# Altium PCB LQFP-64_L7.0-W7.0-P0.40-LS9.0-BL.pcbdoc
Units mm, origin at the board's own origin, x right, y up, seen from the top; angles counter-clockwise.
Board outline 22.4 x 22.6 mm, 2 copper layers (Top Layer, Bottom Layer); 1 components, 0 nets, 64 pads, 0 vias.
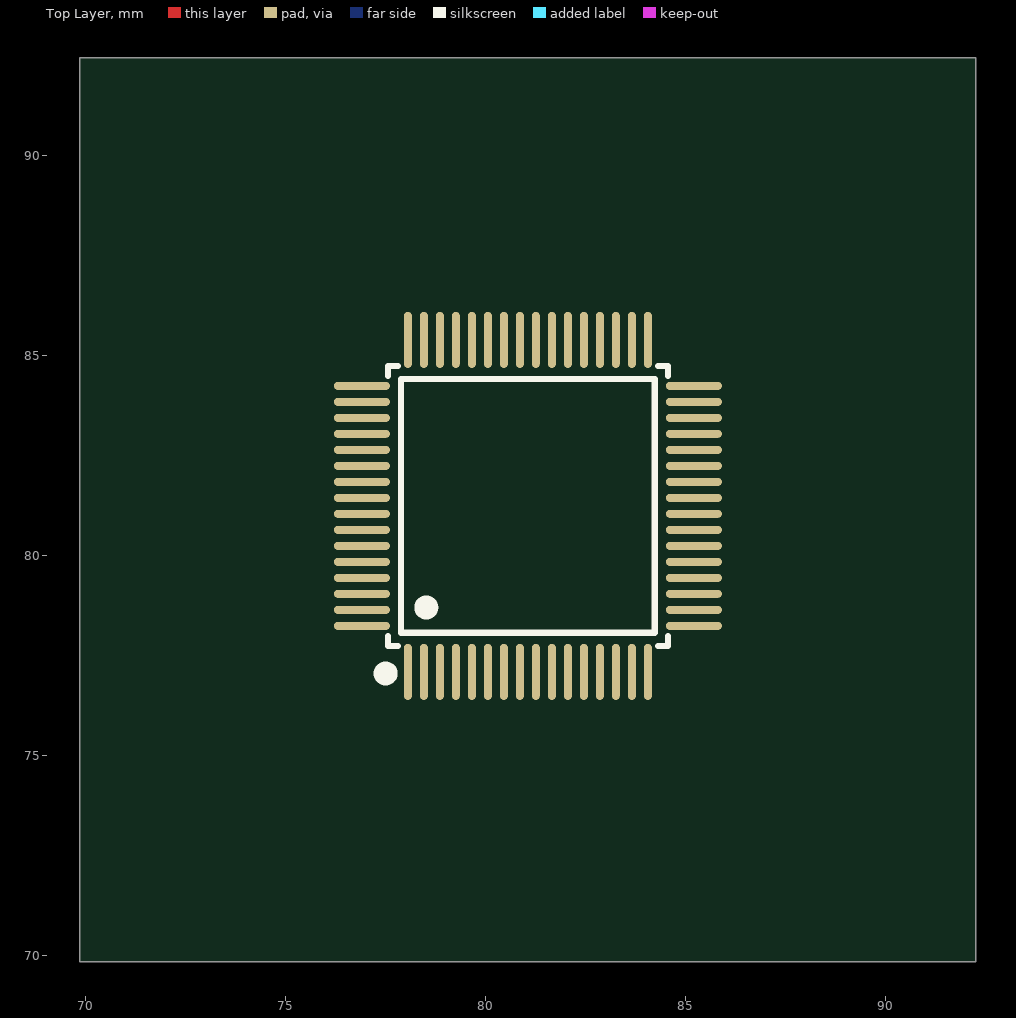
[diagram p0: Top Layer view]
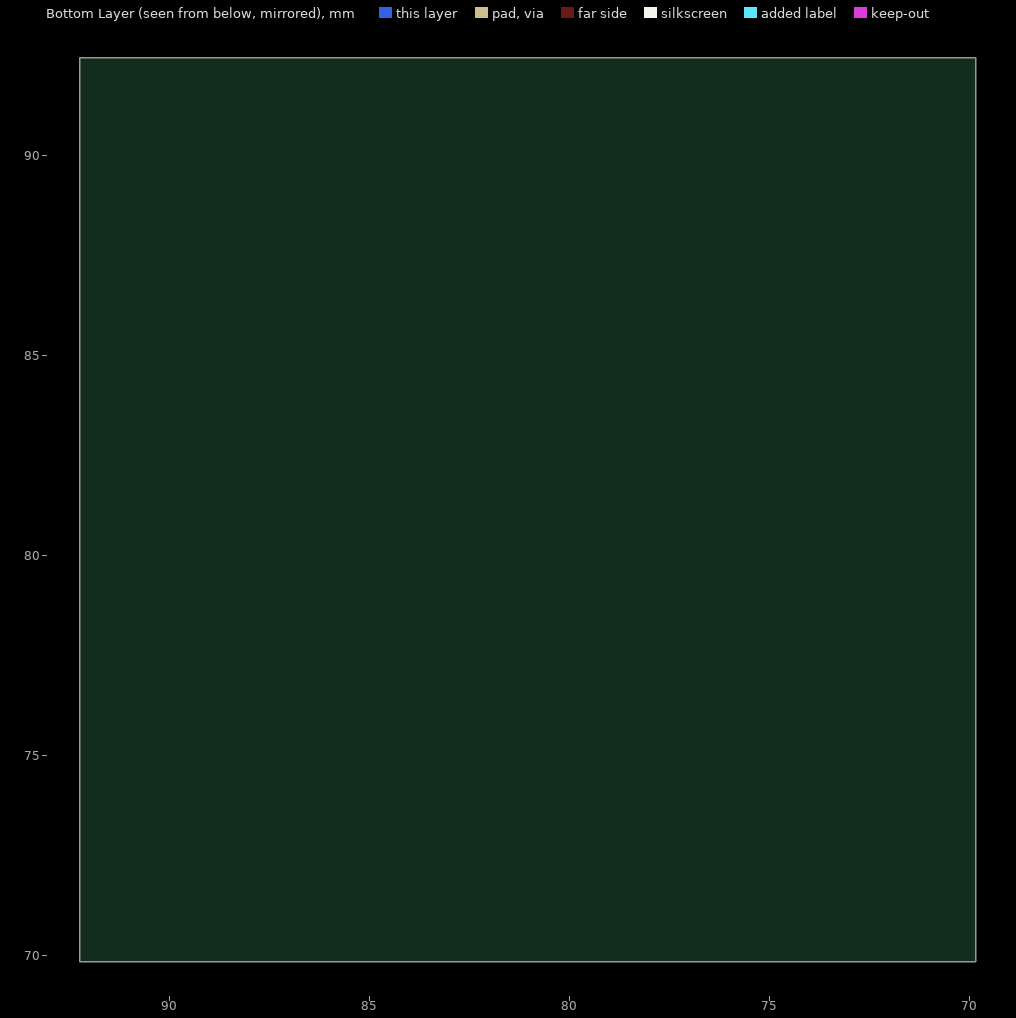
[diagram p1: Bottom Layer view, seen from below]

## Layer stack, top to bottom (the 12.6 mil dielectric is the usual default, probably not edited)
Top Layer: signal copper (thickness not stored)
Dielectric: dielectric 0.32, FR-4, Dk 4.8
Bottom Layer: signal copper (thickness not stored)

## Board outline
92.25,69.85 69.85,69.85 69.85,92.45 92.25,92.45

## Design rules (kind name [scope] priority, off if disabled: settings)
BoardOutlineClearance safeClearance [All] p0: genericclearance=0.254 ignorepadtopadclearanceinfootprint=FALSE except(0: Arc-SplitContinuation Track-SplitContinuation SMDPad-SplitContinuation THPad-SplitContinuation Via-SplitContinuation Fill-SplitContinuation Poly-SplitContinuation Region-SplitContinuation Text-SplitContinuation; 0.152: Track-CutoutEdge SMDPad-CutoutEdge THPad-CutoutEdge Via-CutoutEdge Fill-CutoutEdge Region-CutoutEdge; 0.3: Track-OutlineEdge SMDPad-OutlineEdge THPad-OutlineEdge Via-OutlineEdge Fill-OutlineEdge Region-OutlineEdge Poly-OutlineEdge Text-OutlineEdge)
Clearance safeClearance [All] p1: gap=0.178 ignorepadtopadclearanceinfootprint=FALSE except(0.152: Track-Track Track-SMDPad SMDPad-SMDPad Track-THPad SMDPad-THPad THPad-THPad Track-Via SMDPad-Via THPad-Via Via-Via Track-Fill SMDPad-Fill THPad-Fill Via-Fill Fill-Fill Track-Region SMDPad-Region THPad-Region Via-Region Fill-Region Region-Region Track-Poly SMDPad-Poly THPad-Poly Via-Poly Fill-Poly Region-Poly Poly-Poly Track-Text SMDPad-Text THPad-Text Via-Text Fill-Text Region-Text Poly-Text Text-Text; 0.175: Track-Hole SMDPad-Hole THPad-Hole Via-Hole Fill-Hole Region-Hole Poly-Hole Text-Hole Sheet-Hole; 0.3: Track-Sheet SMDPad-Sheet THPad-Sheet Via-Sheet Fill-Sheet Region-Sheet Poly-Sheet Text-Sheet)
DiffPairsRouting differentialPair [All] p1: maxuncoupledlength=10 minlimit=6 maxlimit=6 mostfreqgap=6 toplayer_minwidth=5 toplayer_prefwidth=10 toplayer_maxwidth=100 bottomlayer_minwidth=5 bottomlayer_prefwidth=10 bottomlayer_maxwidth=100
PasteMaskExpansion pasteMaskExpansion [All] p1: expansion=0
PlaneConnect innerPlane [All] p1: planeconnectstyle=Relief reliefexpansion=0.508 reliefentries=4 reliefconductorwidth=0.254 reliefairgap=0.254
PolygonConnect copperRegion [All] p1: connectstyle=Relief reliefentries=4 reliefconductorwidth=10 polygonreliefangle="90 Angle" airgapwidth=10
RoutingVias viaSize [All] p1: viastyle="Through Hole" holewidth=12.0078 minholewidth=11.811 maxholewidth=236.2204 width=24.0158 minwidth=19.685 maxwidth=393.7008
SolderMaskExpansion solderMaskExpansion [All] p1: useseparateexpansions=TRUE expansion=2 expansionbottom=2
Width trackWidth [All] p1: maxlimit=100 minlimit=5 preferedwidth=10

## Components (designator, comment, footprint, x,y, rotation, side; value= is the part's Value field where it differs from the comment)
? "LQFP-64_L7.0-W7.0-P0.40-LS9.0-BL" LQFP-64_L7.0-W7.0-P0.40-LS9.0-BL 81.05,81.25 r0 top

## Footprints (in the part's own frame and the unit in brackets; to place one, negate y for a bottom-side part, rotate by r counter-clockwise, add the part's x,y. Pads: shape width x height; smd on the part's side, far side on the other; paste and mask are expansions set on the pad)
LQFP-64_L7.0-W7.0-P0.40-LS9.0-BL [mm]
  oval 0.2x1.4 smd: 1(-3,-4.15) 2(-2.6,-4.15) 3(-2.2,-4.15) 4(-1.8,-4.15) 5(-1.4,-4.15) 6(-1,-4.15) 7(-0.6,-4.15) 8(-0.2,-4.15) 9(0.2,-4.15) 10(0.6,-4.15) 11(1,-4.15) 12(1.4,-4.15) 13(1.8,-4.15) 14(2.2,-4.15) 15(2.6,-4.15) 16(3,-4.15) 33(3,4.15) 34(2.6,4.15) 35(2.2,4.15) 36(1.8,4.15) 37(1.4,4.15) 38(1,4.15) 39(0.6,4.15) 40(0.2,4.15) 41(-0.2,4.15) 42(-0.6,4.15) 43(-1,4.15) 44(-1.4,4.15) 45(-1.8,4.15) 46(-2.2,4.15) 47(-2.6,4.15) 48(-3,4.15)
  oval 1.4x0.2 smd: 17(4.15,-3) 18(4.15,-2.6) 19(4.15,-2.2) 20(4.15,-1.8) 21(4.15,-1.4) 22(4.15,-1) 23(4.15,-0.6) 24(4.15,-0.2) 25(4.15,0.2) 26(4.15,0.6) 27(4.15,1) 28(4.15,1.4) 29(4.15,1.8) 30(4.15,2.2) 31(4.15,2.6) 32(4.15,3) 49(-4.15,3) 50(-4.15,2.6) 51(-4.15,2.2) 52(-4.15,1.8) 53(-4.15,1.4) 54(-4.15,1) 55(-4.15,0.6) 56(-4.15,0.2) 57(-4.15,-0.2) 58(-4.15,-0.6) 59(-4.15,-1) 60(-4.15,-1.4) 61(-4.15,-1.8) 62(-4.15,-2.2) 63(-4.15,-2.6) 64(-4.15,-3)
  silkscreen extent -3.71,-4.34 3.5,3.5

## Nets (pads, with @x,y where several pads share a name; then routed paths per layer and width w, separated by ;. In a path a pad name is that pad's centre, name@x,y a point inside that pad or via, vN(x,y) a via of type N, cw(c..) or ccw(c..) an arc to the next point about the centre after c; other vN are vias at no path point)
pads on no net: ?.1 ?.2 ?.3 ?.4 ?.5 ?.6 ?.7 ?.8 ?.9 ?.10 ?.11 ?.12 ?.13 ?.14 ?.15 ?.16 ?.17 ?.18 ?.19 ?.20 ?.21 ?.22 ?.23 ?.24 ?.25 ?.26 ?.27 ?.28 ?.29 ?.30 ?.31 ?.32 ?.33 ?.34 ?.35 ?.36 ?.37 ?.38 ?.39 ?.40 ?.41 ?.42 ?.43 ?.44 ?.45 ?.46 ?.47 ?.48 ?.49 ?.50 ?.51 ?.52 ?.53 ?.54 ?.55 ?.56 ?.57 ?.58 ?.59 ?.60 ?.61 ?.62 ?.63 ?.64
